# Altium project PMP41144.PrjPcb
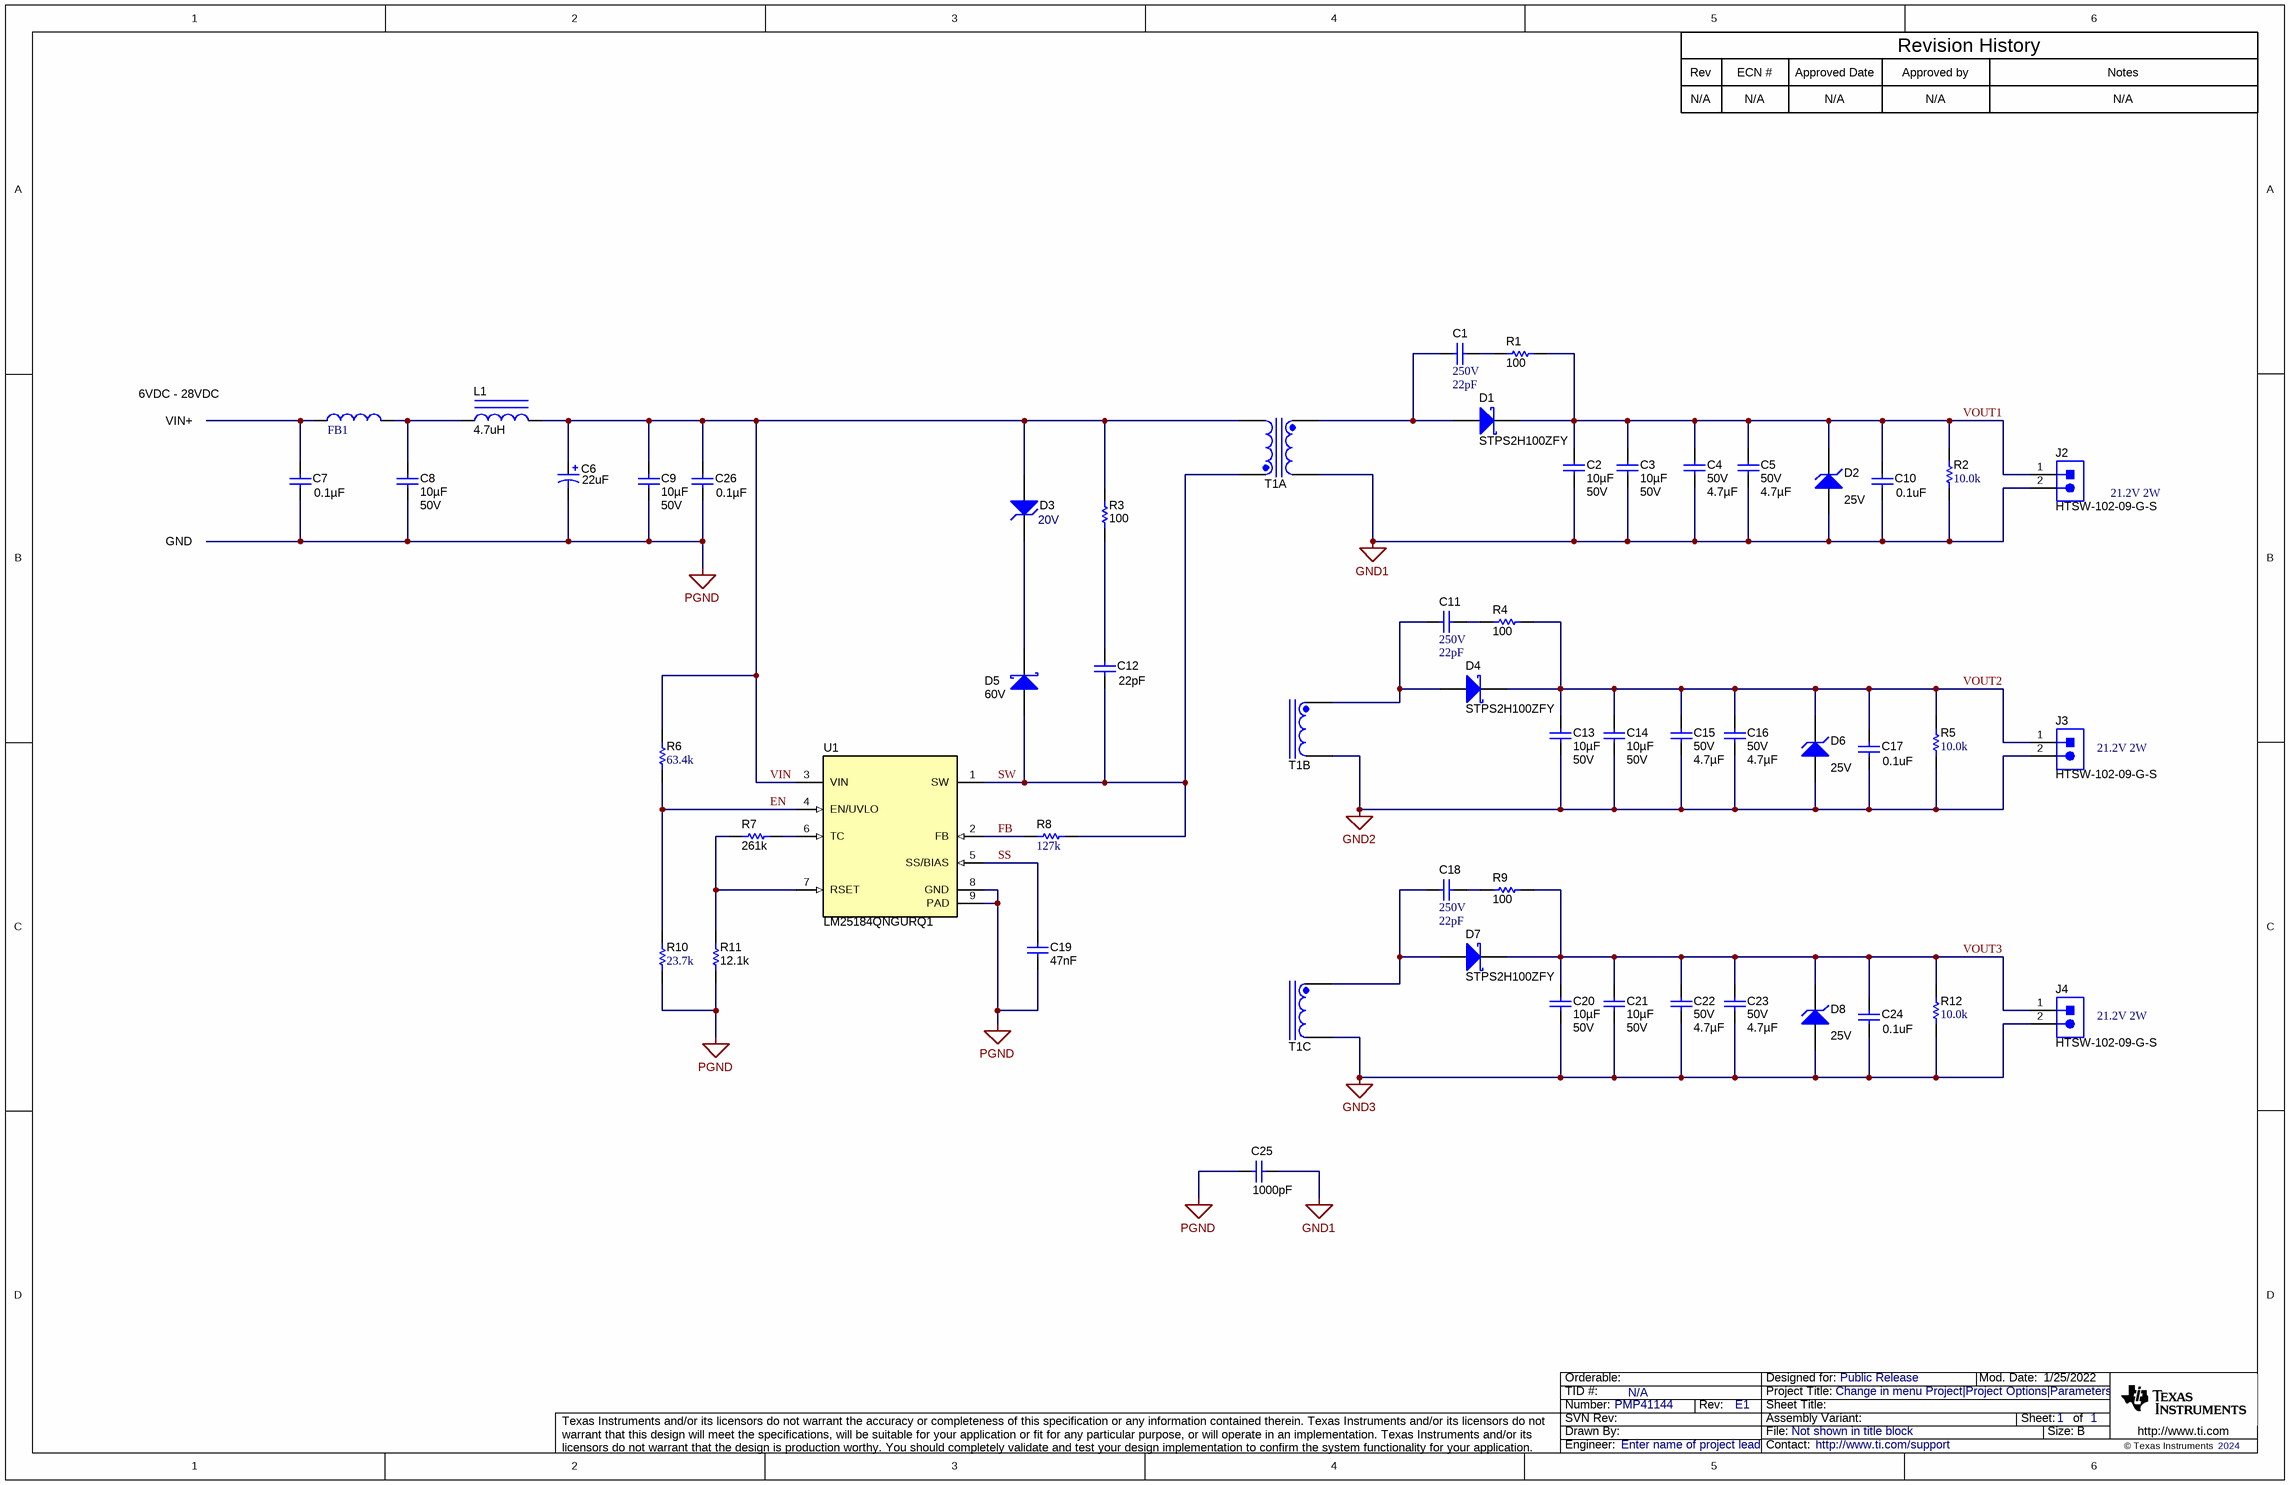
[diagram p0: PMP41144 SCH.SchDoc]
TID: N/A; TechSupport: http://www.ti.com/support; SCH_Rev: E1; PRJ_Title: Change in menu Project|Project Options|Parameters; PRJ_Number: PMP41144; PRJ_Engineer: Enter name of project lead; PRJ_Customer: Public Release; PCB_Rev: E1; PCB_Layout: Who did the Layout?; CopyrightYear: 2024
1 sheet, 53 parts. Net scope: global (net labels, ports and power ports of the same name join across sheets).
Board file: PMP41144 PCB.PcbDoc

## Sheet PMP41144 SCH.SchDoc
size 431 x 279 mm; Date: Not shown in title block; ApprovedBy: Not shown in title block; CheckedBy: Not shown in title block; Author: Not shown in title block; CompanyName: Not shown in title block; Engineer: Not shown in title block; Organization: Not shown in title block; Address1: Not shown in title block; Address2: Not shown in title block; Address3: Not shown in title block; Address4: Not shown in title block; DocumentNumber: 1; Revision: Use project parameter SCH_Rev; SheetNumber: 1; SheetTotal: 1; PageSetup: Record=PageOptions¦CenterHorizontal=True¦CenterVertical=True¦PrintScale=1.00¦XCorrection=1.00¦YCorrection=1.00¦PrintKind=0¦BorderSize=5000000¦LeftOffset=0¦BottomOffset=0¦Orientation=2¦PaperLength=1000¦PaperWidth=1000¦Scale=100¦PaperSource=15¦PrintQuality=600¦MediaType=1¦DitherType=10¦PaperKind=Letter¦PrintScaleMode=1

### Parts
C1  VDC_V: 250V  ValueDisplayed: 22pF  [0805_HV]  (hidden comment: GRM21A5C2E220JW01D)
C2  ValueDisplayed: 10µF  VDC_V: 50V  [1206_190]  (hidden comment: CGA5L1X7R1H106K160AC)
C3  ValueDisplayed: 10µF  VDC_V: 50V  [1206_190]  (hidden comment: CGA5L1X7R1H106K160AC)
C4  VDC_V: 50V  ValueDisplayed: 4.7µF  [1206_190]  (hidden comment: CGA5L3X7R1H475K160AE)
C5  VDC_V: 50V  ValueDisplayed: 4.7µF  [1206_190]  (hidden comment: CGA5L3X7R1H475K160AE)
C6  ValueDisplayed: 22uF  [Panasonic_D]  (hidden comment: EEH-ZC1H220P)
C7  ValueDisplayed: 0.1µF  [0603]  (hidden comment: C0603C104K5RACAUTO)
C8  ValueDisplayed: 10µF  VDC_V: 50V  [1206_190]  (hidden comment: CGA5L1X7R1H106K160AC)
C9  ValueDisplayed: 10µF  VDC_V: 50V  [1206_190]  (hidden comment: CGA5L1X7R1H106K160AC)
C10  value 0.1uF  [0603]  (hidden comment: C0603C104K5RACAUTO)
C11  VDC_V: 250V  ValueDisplayed: 22pF  [0805_HV]  (hidden comment: GRM21A5C2E220JW01D)
C12  ValueDisplayed: 22pF  [0603]  (hidden comment: GRM1885C2A220JA01D)
C13  ValueDisplayed: 10µF  VDC_V: 50V  [1206_190]  (hidden comment: CGA5L1X7R1H106K160AC)
C14  ValueDisplayed: 10µF  VDC_V: 50V  [1206_190]  (hidden comment: CGA5L1X7R1H106K160AC)
C15  VDC_V: 50V  ValueDisplayed: 4.7µF  [1206_190]  (hidden comment: CGA5L3X7R1H475K160AE)
C16  VDC_V: 50V  ValueDisplayed: 4.7µF  [1206_190]  (hidden comment: CGA5L3X7R1H475K160AE)
C17  value 0.1uF  [0603]  (hidden comment: C0603C104K5RACAUTO)
C18  VDC_V: 250V  ValueDisplayed: 22pF  [0805_HV]  (hidden comment: GRM21A5C2E220JW01D)
C19  Cap_F: 47nF  [0603]  (hidden comment: GCM188R71E473KA37D)
C20  ValueDisplayed: 10µF  VDC_V: 50V  [1206_190]  (hidden comment: CGA5L1X7R1H106K160AC)
C21  ValueDisplayed: 10µF  VDC_V: 50V  [1206_190]  (hidden comment: CGA5L1X7R1H106K160AC)
C22  VDC_V: 50V  ValueDisplayed: 4.7µF  [1206_190]  (hidden comment: CGA5L3X7R1H475K160AE)
C23  VDC_V: 50V  ValueDisplayed: 4.7µF  [1206_190]  (hidden comment: CGA5L3X7R1H475K160AE)
C24  value 0.1uF  [0603]  (hidden comment: C0603C104K5RACAUTO)
C25  ValueDisplayed: 1000pF  [1206_190]  (hidden comment: 202R18W102KV4E)
C26  ValueDisplayed: 0.1µF  [0603]  (hidden comment: C0603C104K5RACAUTO)
D1  STPS2H100ZFY  [SOD-123F]
D2  value 25V  [SOD-123]  (hidden comment: MMSZ4710-HE3-08)
D3  value 20V  [SMA]  (hidden comment: 3SMAJ5932B-TP)
D4  STPS2H100ZFY  [SOD-123F]
D5  value 60V  [SOD-123W]  (hidden comment: PMEG60T30ELRX)
D6  value 25V  [SOD-123]  (hidden comment: MMSZ4710-HE3-08)
D7  STPS2H100ZFY  [SOD-123F]
D8  value 25V  [SOD-123]  (hidden comment: MMSZ4710-HE3-08)
FB1  782853611  [WE-CBA_0805_L2W1.2H0.9_HC]  (value not drawn)
J2  HTSW-102-09-G-S  [Samtec_HTSW-102-09-x-S]
J3  HTSW-102-09-G-S  [Samtec_HTSW-102-09-x-S]
J4  HTSW-102-09-G-S  [Samtec_HTSW-102-09-x-S]
L1  ValueDisplayed: 4.7uH  [XFL4030]  (hidden comment: XFL4030-472MEB)
R1  ValueDisplayed: 100  [0603]  (hidden comment: CRCW0603100RFKEA)
R2  ValueDisplayed: 10.0k  [1206]  (hidden comment: CRCW120610K0FKEAHP)
R3  ValueDisplayed: 100  [0603]  (hidden comment: CRCW0603100RFKEA)
R4  ValueDisplayed: 100  [0603]  (hidden comment: CRCW0603100RFKEA)
R5  ValueDisplayed: 10.0k  [1206]  (hidden comment: CRCW120610K0FKEAHP)
R6  ValueDisplayed: 63.4k  [0603]  (hidden comment: CRCW060363K4FKEA)
R7  ValueDisplayed: 261k  [0603]  (hidden comment: CRCW0603261KFKEA)
R8  ValueDisplayed: 127k  [0603]  (hidden comment: CRCW0603127KFKEA)
R9  ValueDisplayed: 100  [0603]  (hidden comment: CRCW0603100RFKEA)
R10  ValueDisplayed: 23.7k  [0603]  (hidden comment: CRCW060323K7FKEA)
R11  ValueDisplayed: 12.1k  [0603]  (hidden comment: CRCW060312K1FKEA)
R12  ValueDisplayed: 10.0k  [1206]  (hidden comment: CRCW120610K0FKEAHP)
T1  750345026  [PMP41104 Transformer]  (value not drawn)  (parts A,B,C of 5)
U1  LM25184QNGURQ1  [NGU0008C]

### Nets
GND1: C2.2 C3.2 C4.2 C5.2 C10.2 C25.1 D2.2(A) J2.2 R2.1 T1.8
GND2: C13.2 C14.2 C15.2 C16.2 C17.2 D6.2(A) J3.2 R5.1 T1.14
GND3: C20.2 C21.2 C22.2 C23.2 C24.2 D8.2(A) J4.2 R12.1 T1.12
PGND: C6.2(-) C7.2 C8.2 C9.2 C19.2 C25.2 C26.2 R10.1 R11.1 U1.8(GND) U1.9(PAD)
EN: R6.1 R10.2 U1.4(EN/UVLO)
FB: R8.1 U1.2(FB)
SS: C19.1 U1.5(SS/BIAS)
SW: C12.2 D5.2(A) R8.2 T1.2 U1.1(SW)
VIN: C6.1(+) C9.1 C26.1 D3.2(A) L1.2 R3.2 R6.2 T1.4 U1.3(VIN)
VOUT1: C2.1 C3.1 C4.1 C5.1 C10.1 D1.1(K) D2.1(K) J2.1 R1.1 R2.2
VOUT2: C13.1 C14.1 C15.1 C16.1 C17.1 D4.1(K) D6.1(K) J3.1 R4.1 R5.2
VOUT3: C20.1 C21.1 C22.1 C23.1 C24.1 D7.1(K) D8.1(K) J4.1 R9.1 R12.2
NetC1_1: C1.1 R1.2
NetC1_2: C1.2 D1.2(A) T1.7
NetC7_1: C7.1 FB1.1
NetC8_1: C8.1 FB1.2 L1.1
NetC11_1: C11.1 R4.2
NetC11_2: C11.2 D4.2(A) T1.15
NetC12_1: C12.1 R3.1
NetC18_1: C18.1 R9.2
NetC18_2: C18.2 D7.2(A) T1.13
NetD3_1: D3.1(K) D5.1(K)
NetR7_1: R7.1 R11.2 U1.7(RSET)
NetR7_2: R7.2 U1.6(TC)

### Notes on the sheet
- Rev
- N/A
- ECN #
- Approved Date
- Approved by
- Revision History
- Notes
- VIN+
- 6VDC - 28VDC
- 21.2V 2W
- GND
- (near J3) 21.2V 2W
- (near J4) 21.2V 2W

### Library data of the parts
C1 C11 C18 = CMP-0008240-1: CAP, CERM, 22 pF, 250 V, +/- 5%, C0G/NP0, 0805; Manufacturer: MuRata; TaMin_C: -55°C; Polarized: N; SizeAreaWB_mm2: 6.75; Value1: Unknown; U/M: EA; Value: 22pF; TaMax_C: 125°C; SizeZ_mm: 1.45; SizeX_mm: 2; SizeY_mm: 1.25; Cap_Case: 0805; SizeArea_mm2: 2.5; AEC Category: Q200
C2 C3 C8 C9 C13 C14 C20 C21 = CMP-0085950-1: CAP, CERM, 10 µF, 50 V,+/- 10%, X7R, AEC-Q200 Grade 1, 1206; Manufacturer: TDK; SizeZ_mm: 1.9; Value: 10uF; Cap_Case: 1206; AEC Grade: 1; TaMin_C: -55°C; U/M: EA; SizeArea_mm2: 5.12; TaMax_C: 125°C; AEC Qualified: Y; AEC Category: Q200; SizeX_mm: 3.2; SizeY_mm: 1.6; Polarized: N; SizeAreaWB_mm2: 10.92
C4 C5 C15 C16 C22 C23 = CMP-0085349-1: CAP, CERM, 4.7 µF, 50 V,+/- 10%, X7R, AEC-Q200 Grade 1, 1206; Manufacturer: TDK; SizeZ_mm: 1.9; Polarized: N; AEC Category: Q200; SizeY_mm: 1.6; SizeAreaWB_mm2: 10.92; SizeArea_mm2: 5.12; Value: 4.7uF; TaMin_C: -55°C; AEC Qualified: Y; SizeX_mm: 3.2; AEC Grade: 1; Cap_Case: 1206; U/M: EA; TaMax_C: 125°C
C6 = CMP-0012597-3: CAP, Polymer Hybrid, 22 uF, 50 V, +/- 20%, 0.08 ohm, AEC-Q200 Grade 1, D6.3xL5.8mm SMD; Manufacturer: Panasonic; TaMin_C: -55°C; ESR_ohm: 0.08; Polarized: Y; SizeAreaWB_mm2: 73.96; Value: 22uF; TaMax_C: 125°C; SizeZ_mm: 6.1; SizeX_mm: 6.6; Cap_Case: 6.3x5.8; Value2: 50V; SizeArea_mm2: 43.56; CompType: Capacitor; Cap_F: 22µF; IRMS_A: 750mA; AEC Grade: 1; AEC Category: Q200
C7 C26 = CMP-0079602-1: CAP, CERM, 0.1 µF, 50 V,+/- 10%, X7R, AEC-Q200 Grade 1, 0603; Manufacturer: Kemet; TaMin_C: -55°C; Polarized: N; SizeAreaWB_mm2: 4.68; U/M: EA; Value: 0.1uF; TaMax_C: 125°C; SizeZ_mm: 1; SizeX_mm: 1.6; SizeY_mm: 0.8; Value2: 50V; SizeArea_mm2: 1.28; AEC Qualified: Y; Cap_F: 100nF; AEC Category: Q200
C10 C17 C24 = CMP-0079602-1: CAP, CERM, 0.1 µF, 50 V,+/- 10%, X7R, AEC-Q200 Grade 1, 0603; Manufacturer: Kemet; TaMin_C: -55°C; Polarized: N; SizeAreaWB_mm2: 4.68; U/M: EA; TaMax_C: 125°C; SizeZ_mm: 1; SizeX_mm: 1.6; SizeY_mm: 0.8; Value2: 50V; SizeArea_mm2: 1.28; AEC Qualified: Y; Cap_F: 100nF; AEC Category: Q200; ValueDisplayed: 0.1µF
C12 = CMP-0007255-4: CAP, CERM, 22 pF, 100 V, +/- 5%, C0G/NP0, 0603; Manufacturer: MuRata; TaMin_C: -55°C; Polarized: N; SizeAreaWB_mm2: 4.68; Value1: Unknown; U/M: EA; Value: 22pF; TaMax_C: 125°C; SizeZ_mm: 1; SizeX_mm: 1.6; SizeY_mm: 0.8; Value2: 100V; SizeArea_mm2: 1.28; CompType: Capacitor; AEC Category: Q200
C19 = CMP-0007141-3: CAP, CERM, 0.047 uF, 25 V, +/- 10%, X7R, AEC-Q200 Grade 1, 0603; Manufacturer: MuRata; TaMin_C: -55°C; Polarized: N; SizeAreaWB_mm2: 4.68; Value1: Unknown; U/M: EA; TaMax_C: 125°C; SizeZ_mm: 1; SizeX_mm: 1.6; SizeY_mm: 0.8; Value2: 25V; SizeArea_mm2: 1.28; AEC Qualified: Y; AEC Category: Q200
C25 = CMP-0008572-2: CAP, CERM, 1000 pF, 2000 V, +/- 10%, X7R, 1206_190; Manufacturer: Johanson Technology; TaMin_C: -55°C; Polarized: N; SizeAreaWB_mm2: 10.92; Value1: Unknown; U/M: EA; Value: 1000pF; TaMax_C: 125°C; SizeZ_mm: 1.9; SizeX_mm: 3.2; SizeY_mm: 1.6; Cap_Case: 1206; Value2: 2000V; SizeArea_mm2: 5.12; CompType: Capacitor; Cap_F: 1nF; VDC_V: 2kV; AEC Category: Q200
D1 D4 D7 = CMP-0080011-2: Diode, Schottky, 100 V, 2 A, AEC-Q101, SOD-123F; Manufacturer: STMicroelectronics; Vr_V: 100V; Value1: 2A; SizeZ_mm: 1.1; TJmax_C: 175°C; AEC Category: Q101; SizeY_mm: 1.6; Value2: 0.5V; AEC Qualified: Y; SizeAreaWB_mm2: 11.7; Vf_V: 500mV; SizeX_mm: 3.5; Value: 100V; SizeArea_mm2: 5.6
D2 D6 D8 = CMP-0077583-1: Diode, Zener, 25 V, 500 mW, AEC-Q101, SOD-123; Manufacturer: Vishay-Semiconductor; SizeAreaWB_mm2: 13.095; SizeArea_mm2: 6.545; AEC Qualified: Y; AEC Category: Q101; SizeZ_mm: 1.35; RJA_CperW: 340; Power_W: 500mW; SizeY_mm: 1.7; U/M: EA; Value1: 0.5W; SizeX_mm: 3.85
D3 = CMP-0005511-4: Diode, Zener, 20 V, 3 W, SMA; Manufacturer: Micro Commercial Components; SizeArea_mm2: 16.3228; Power_W: 3W; SizeAreaWB_mm2: 37.3428; SizeY_mm: 2.92; AEC Category: Q101; RJA_CperW: 226; SizeZ_mm: 2.87; SizeX_mm: 5.59
D5 = CMP-0085903-1: Diode, Schottky, 60 V, 3 A, AEC-Q101, SOD-123W; Manufacturer: Nexperia; Io_A: 3A; SizeAreaWB_mm2: 12.15; TJmax_C: 175°C; SizeZ_mm: 1; SizeX_mm: 3.5; SizeY_mm: 1.7; Vf_V: 620mV; Value2: 0.62V; SizeArea_mm2: 5.95; AEC Qualified: Y; AEC Category: Q101
FB1 = CMP-0066722-1: WE-CBA SMT EMI Suppression Ferrite Bead, size 0805, 600Ohm, 2A; Manufacturer: Wurth Elektronik; Case/Size Code: 0805; DC Resistance Max: 0.11Ohm; Impedance Max: 700Ohm; Type: High Current
J2-J4 = CMP-0075626-1: Header, 100mil, 2x1, Gold, TH; Manufacturer: Samtec; Pitch_mm: 2.54; Gender: Male; Cert_CSA: Y; CT: False; Row_Count: 1
L1 = CMP-0061153-1: Inductor, Shielded, Composite, 4.7 uH, 2.1 A, 0.03 ohm, SMD; Manufacturer: Coilcraft; Isat: 2.1A @ 30% inductance drop; Irms: 7.5A @ 40C rise; Green_Lifecycle: Not Set; SizeAreaWB_mm2: 25; DCR_ohm: 0.03; Green_REACh: Incomplete; Value: 4.7uH; Imax_A: 2.1A; SizeZ_mm: 3.1; SizeX_mm: 4; SizeArea_mm2: 16; Ind_H: 4.7µH; AEC Qualified: N; AEC Category: Q200
R1 R3 R4 R9 = CMP-0021991-4: RES, 100, 1%, 0.1 W, AEC-Q200 Grade 0, 0603; Manufacturer: Vishay-Dale; Power_W: 100mW; TempCo: 100 ppm/C; Value_Code: 100R; Value: 100; EIA_Code: E96; SizeX_mm: 1.6; SizeY_mm: 0.8; SizeZ_mm: 1; Value2: 0.1W; SizeArea_mm2: 1.28; AEC Qualified: Y; VDC_V: 75V; AEC Category: Q200; AEC Grade: 0
R2 R5 R12 = CMP-0016578-1: RES, 10.0 k, 1%, 0.5 W, 1206; Manufacturer: Vishay-Dale; Power_W: 500mW; TempCo: 100 ppm/C; Value_Code: 10k0; U/M: EA; Value: 10.0k; EIA_Code: E96; Res_ohm: 10k; SizeX_mm: 3.2; SizeY_mm: 1.6; SizeZ_mm: 1.35; Value2: 0.5W; SizeArea_mm2: 5.12; AEC Category: Q200
R6 = CMP-0022540-4: RES, 63.4 k, 1%, 0.1 W, AEC-Q200 Grade 0, 0603; Manufacturer: Vishay-Dale; Power_W: 100mW; TempCo: 100 ppm/C; Value_Code: 63k4; Value: 63.4k; EIA_Code: E96; SizeX_mm: 1.6; SizeY_mm: 0.8; SizeZ_mm: 1; Value2: 0.1W; SizeArea_mm2: 1.28; AEC Qualified: Y; VDC_V: 75V; AEC Category: Q200; AEC Grade: 0
R7 = CMP-0022244-4: RES, 261 k, 1%, 0.1 W, AEC-Q200 Grade 0, 0603; Manufacturer: Vishay-Dale; Power_W: 100mW; TempCo: 100 ppm/C; Value: 261k; EIA_Code: E96; SizeX_mm: 1.6; SizeY_mm: 0.8; SizeZ_mm: 1; Value2: 0.1W; SizeArea_mm2: 1.28; AEC Qualified: Y; VDC_V: 75V; AEC Category: Q200; AEC Grade: 0
R8 = CMP-0022028-4: RES, 127 k, 1%, 0.1 W, AEC-Q200 Grade 0, 0603; Manufacturer: Vishay-Dale; Power_W: 100mW; TempCo: 100 ppm/C; Value: 127k; EIA_Code: E96; SizeX_mm: 1.6; SizeY_mm: 0.8; SizeZ_mm: 1; Value2: 0.1W; SizeArea_mm2: 1.28; AEC Qualified: Y; VDC_V: 75V; AEC Category: Q200; AEC Grade: 0
R10 = CMP-0022229-4: RES, 23.7 k, 1%, 0.1 W, AEC-Q200 Grade 0, 0603; Manufacturer: Vishay-Dale; Power_W: 100mW; TempCo: 100 ppm/C; Value_Code: 23k7; Value: 23.7k; EIA_Code: E96; SizeX_mm: 1.6; SizeY_mm: 0.8; SizeZ_mm: 1; Value2: 0.1W; SizeArea_mm2: 1.28; AEC Qualified: Y; VDC_V: 75V; AEC Category: Q200; AEC Grade: 0
R11 = CMP-0022030-4: RES, 12.1 k, 1%, 0.1 W, AEC-Q200 Grade 0, 0603; Manufacturer: Vishay-Dale; Power_W: 100mW; TempCo: 100 ppm/C; Value_Code: 12k1; Value: 12.1k; EIA_Code: E96; SizeX_mm: 1.6; SizeY_mm: 0.8; SizeZ_mm: 1; Value2: 0.1W; SizeArea_mm2: 1.28; AEC Qualified: Y; VDC_V: 75V; AEC Category: Q200; AEC Grade: 0
T1 = XFMR: Manufacturer: Wurth; CompType: Transformer
U1 = CMP-0860959-2: 42-VIN PSR Flyback DC/DC Converter with 65-V, 4-A Integrated MOSFET, NGU0008C (WSON-8); Manufacturer: Texas Instruments; SizeArea_mm2: 16; SizeY_mm: 4; SizeAreaWB_mm2: 25; CompType: IC; AEC Category: Q200; SizeZ_mm: 0.8; AEC Qualified: Y

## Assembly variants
001: not fitted C1 C4 C5 C10 C11 C15 C16 C17 C18 C22 C23 C24 C25 D2 D6 D8 FID1 FID2 FID3 R1 R4 R7 R9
